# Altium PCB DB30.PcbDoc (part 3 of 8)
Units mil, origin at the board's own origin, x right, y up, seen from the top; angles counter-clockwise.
Board outline 3236.22 x 4456.69 mil, 8 copper layers (Top Layer, MidLayer1, MidLayer2, GND-Layer5, MidLayer3, VCC, MidLayer4, Bottom Layer), stack 61.8 mil thick; 219 components, 472 nets, 1811 pads, 1561 vias.
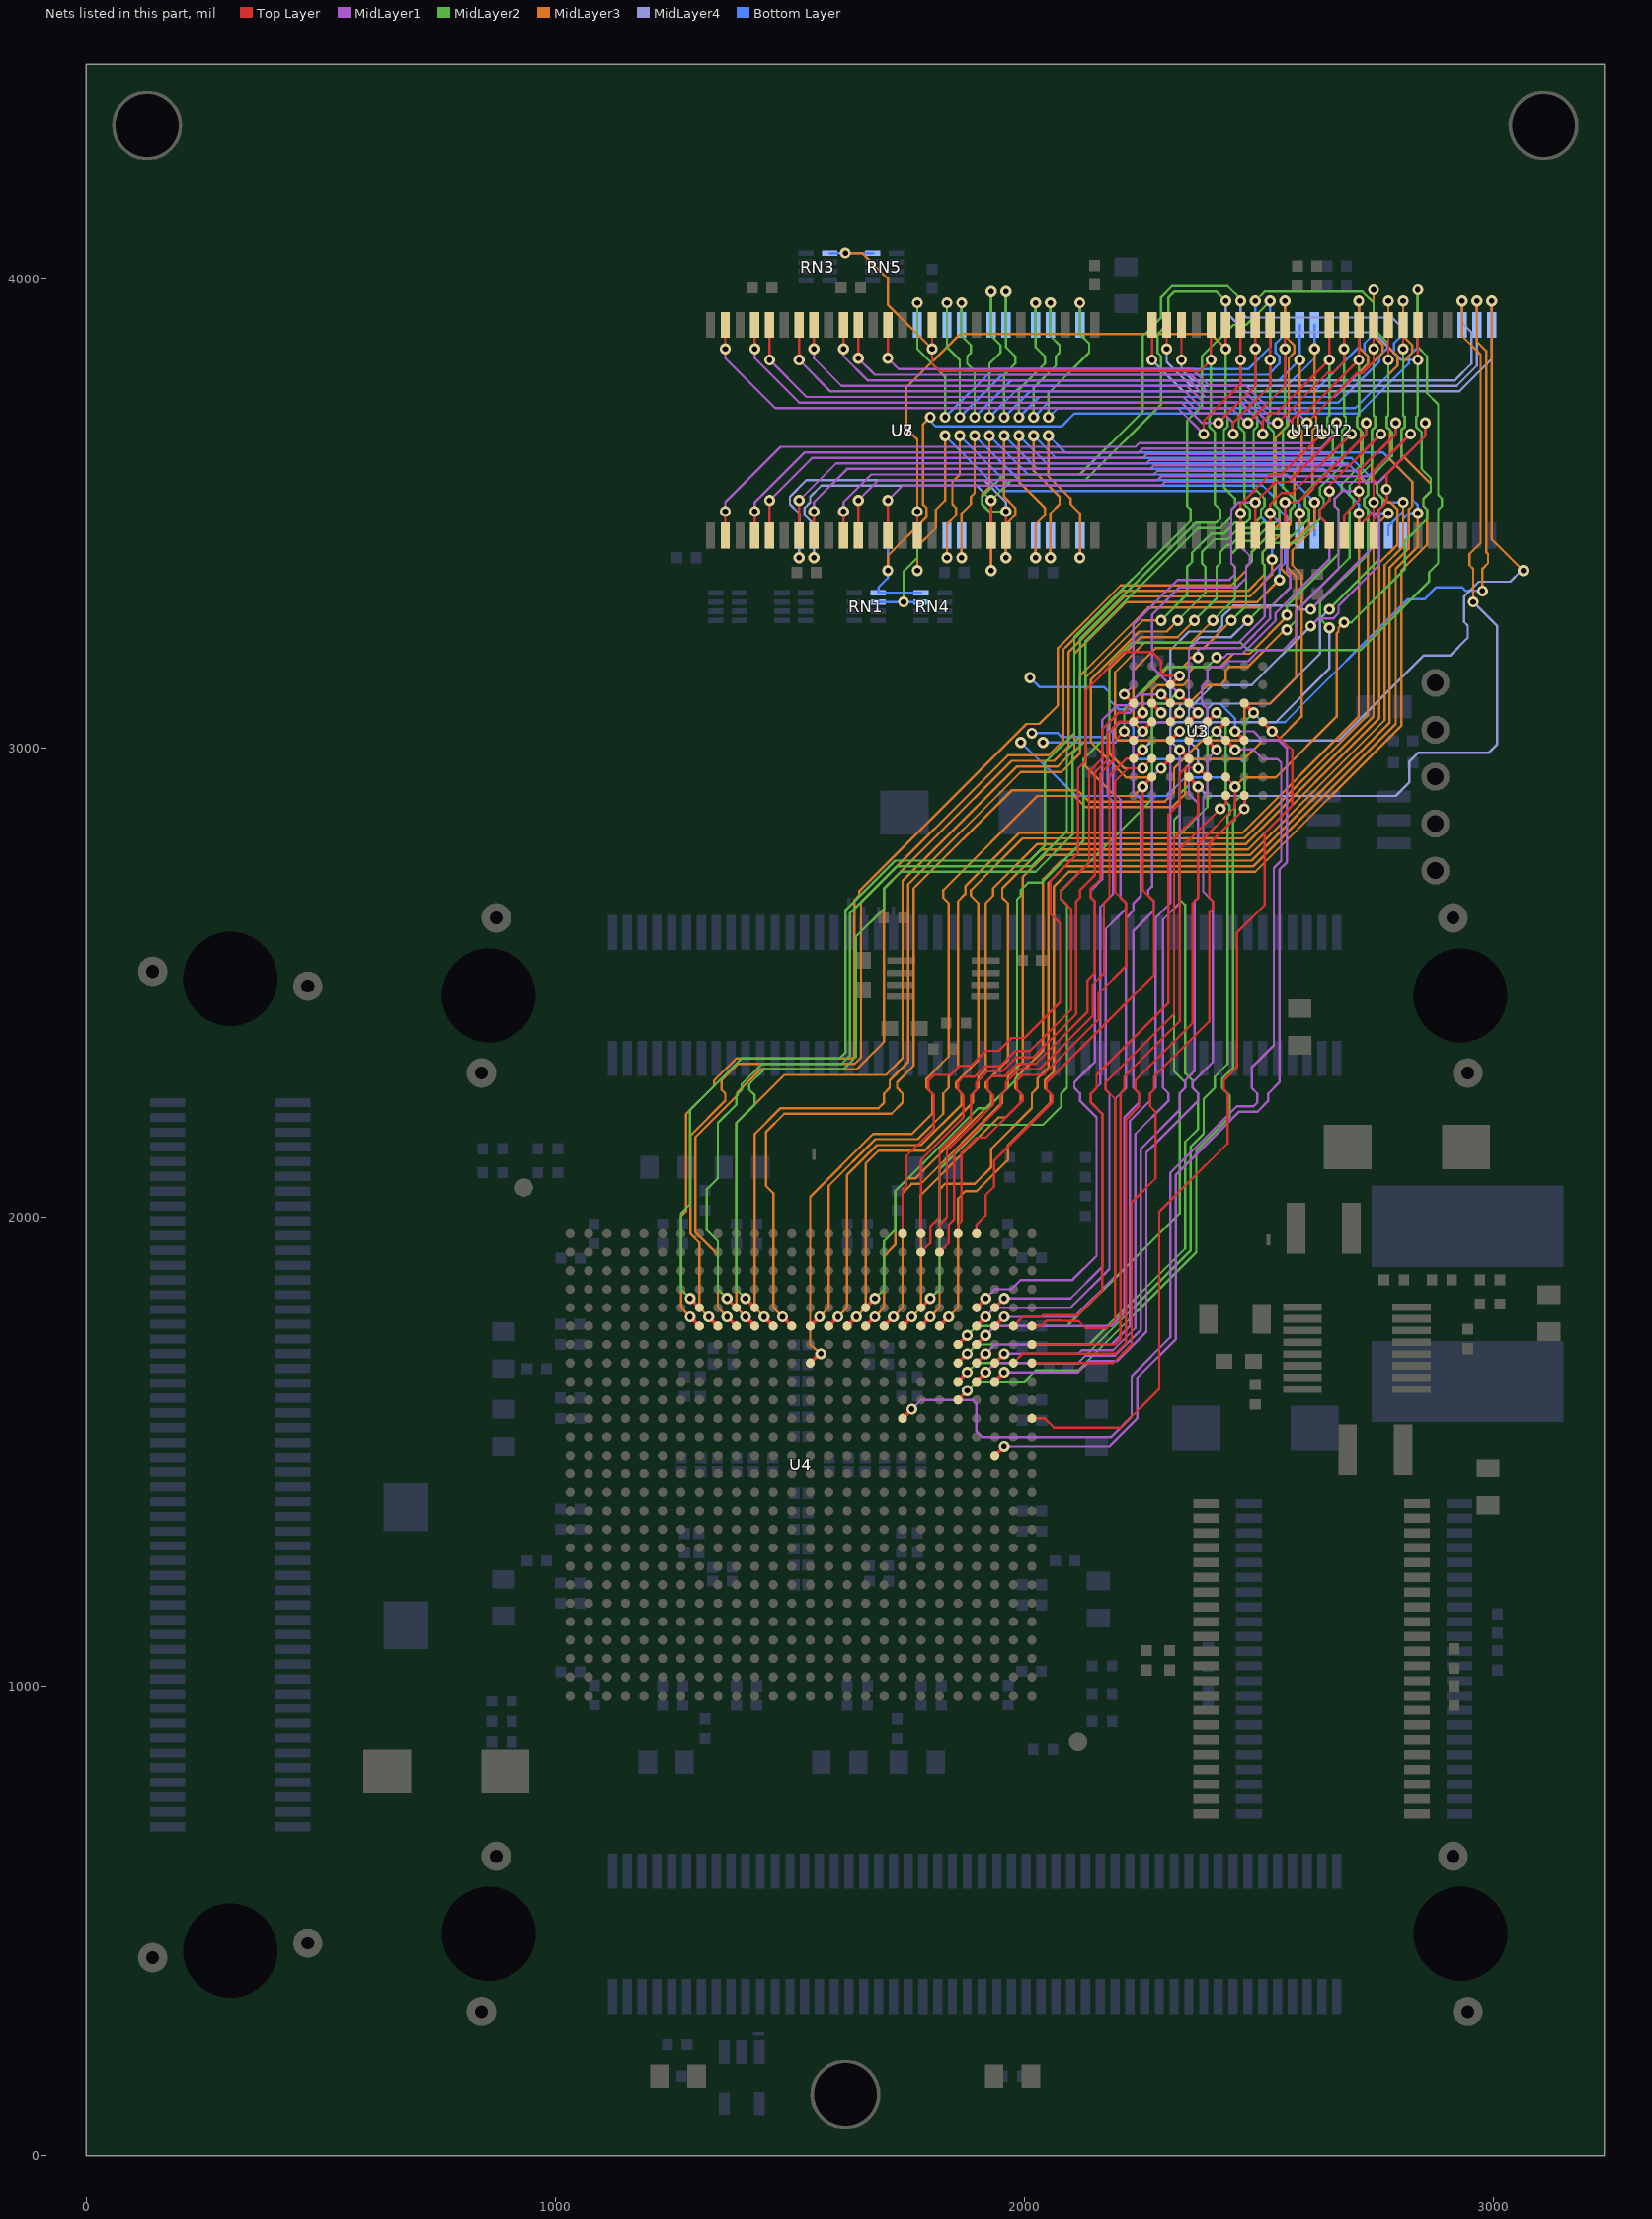
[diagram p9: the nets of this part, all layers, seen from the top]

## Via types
v1: diameter 23.62, hole 11.81, Top Layer to Bottom Layer, 944 vias
v2: diameter 23.62, hole 11.81, Top Layer to Bottom Layer, tented both sides, 477 vias
v3: diameter 27.56, hole 15.75, Top Layer to Bottom Layer, 139 vias
v4: diameter 23.62, hole 11.81, Top Layer to Bottom Layer, tented top, 1 vias

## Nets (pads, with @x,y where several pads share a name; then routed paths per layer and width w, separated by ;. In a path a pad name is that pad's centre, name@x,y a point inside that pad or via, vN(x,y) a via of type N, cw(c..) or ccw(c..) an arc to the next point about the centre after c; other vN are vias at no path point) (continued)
BUS_A15: U3.C7 U4.H25 U7.20 U8.20 U11.26 U12.26 | length 4825.3
  Top Layer w5: U7.20@1929.13,3452.76 v2(1929.13,3527.55) ; U4.H25@1976.38,1688.98 1996.06,1708.66 2078.74,1708.66 2090.55,1708.66 2192.91,1708.66 2216.54,1732.28 2216.54,2208.66 2244.09,2236.22 2244.09,2263.78 2236.22,2271.65 2236.22,2291.34 2358.27,2413.39 2358.27,2669.29 2370.08,2681.1 2370.08,2795.28 2448.82,2874.02 v1(2448.82,2917.32) 2448.82,2918.31 U3.C7@2429.13,2937.99 ; v2(2838.58,3826.77) U11.26@2838.58,3901.57
  MidLayer2 w5: v2(1929.13,3527.55) 1972.44,3570.87 2129.92,3570.87 2291.34,3732.28 2291.34,3834.65 2283.46,3842.52 2283.46,3881.89 2293.31,3891.73 2307.09,3905.51 2307.09,3960.63 2318.9,3972.44 2409.45,3972.44 v2(2429.13,3952.76) ; v1(2681.1,3267.72) 2696.85,3267.72 2811.02,3381.89 2811.02,3440.94 2858.27,3488.19 2858.27,3507.87 2850.39,3515.75 2850.39,3531.5 2866.14,3547.25 2866.14,3574.8 2846.46,3594.49 2846.46,3673.23 2834.64,3685.04 2834.64,3704.72 2838.58,3708.66 v2(2838.58,3826.77)
  MidLayer3 w5: v1(2448.82,2917.32) 2468.5,2937.01 2535.43,2937.01 2665.35,3066.93 2665.35,3244.09 2669.29,3248.03 2669.29,3255.91 v1(2681.1,3267.72)
  MidLayer4 w5: v2(1551.18,3405.51) 1551.18,3476.38 1531.5,3496.06 1531.5,3511.81 1543.31,3523.62 1543.31,3535.43 1566.93,3559.06 1897.63,3559.06 v2(1929.13,3527.55) ; v2(2429.13,3952.76) 2429.13,3929.13 2472.44,3885.83 2744.09,3885.83 2803.15,3826.77 v2(2838.58,3826.77)
  Bottom Layer w5: v2(1551.18,3405.51) U8.20@1551.18,3452.76 ; U12.26@2429.13,3901.57 v2(2429.13,3952.76)
BUS_A16: U3.D7 U4.F25 U7.21 U8.21 U11.27 U12.27 | length 4895
  Top Layer w5: U7.21@1960.63,3452.76 v2(1960.63,3503.93) ; U4.F25@1976.38,1767.72 1996.06,1787.4 2000,1787.4 2031.5,1787.4 2035.43,1787.4 2039.37,1791.34 2078.74,1791.34 2090.55,1791.34 2114.17,1791.34 2165.35,1842.52 2165.35,2220.47 2141.73,2244.09 2141.73,2263.78 2153.54,2275.59 2153.54,2303.15 2307.09,2456.69 2307.09,2858.27 2330.71,2881.89 2330.71,2944.88 2343.51,2957.68 v1@2370.08,2957.68 ; v2(2807.09,3850.39) U11.27@2807.09,3901.57
  Top Layer w7.87: v1@2370.08,2957.68 U3.D7@2389.76,2937.99
  MidLayer2 w5: v2(1960.63,3503.93) 1925.2,3503.93 1909.45,3519.68 1909.45,3535.43 1925.2,3551.18 1956.69,3582.68 2118.11,3582.68 2251.97,3716.54 2251.97,3877.95 2291.34,3917.32 2291.34,3960.63 2314.96,3984.25 2433.07,3984.25 2460.63,3956.69 v2(2460.63,3952.76) ; v1(2649.61,3295.28) 2755.91,3401.57 2755.91,3507.87 2763.78,3515.75 2763.78,3531.5 2751.97,3543.31 2751.97,3562.99 2803.15,3614.17 2803.15,3677.17 2811.02,3685.04 2811.02,3704.72 2807.09,3708.66 v2(2807.09,3850.39)
  MidLayer4 w5: v2(1519.68,3405.51) 1519.68,3500 1500,3519.68 1500,3535.43 1535.43,3570.87 1913.38,3570.87 1960.63,3523.63 v2(1960.63,3503.93) ; v1(2370.08,2956.69) 2370.08,2996.06 2350.39,3015.75 2350.39,3043.31 2362.2,3055.12 2377.95,3055.12 2389.76,3066.93 2389.76,3082.68 2401.57,3094.49 2523.62,3094.49 2629.92,3200.79 2629.92,3275.59 v1(2649.61,3295.28) ; v2(2460.63,3952.76) 2460.63,3929.13 2472.44,3917.32 2783.46,3917.32 2807.09,3893.7 v2(2807.09,3850.39)
  Bottom Layer w5: v2(1519.68,3405.51) U8.21@1519.68,3452.76 ; U12.27@2460.63,3901.57 v2(2460.63,3952.76)
BUS_A17: U3.E7 U4.F26 U11.42 U12.42 | length 4093.1
  Top Layer w5: U4.F26@2015.75,1767.72 2035.43,1767.72 2047.24,1779.53 2078.74,1779.53 2089.57,1778.54 2115.16,1778.54 2129.92,1763.78 2176.18,1763.78 2192.91,1780.51 2192.91,2251.97 2173.23,2271.65 2173.23,2287.4 2318.9,2433.07 2318.9,2807.09 2370.08,2858.27 v1(2370.08,2917.32) ; v2(2334.64,3826.77) U11.42@2334.64,3901.57
  Top Layer w7.87: U3.E7@2350.39,2937.99 v1(2370.08,2917.32)
  MidLayer3 w5: v2(2933.07,3952.76) 2933.07,3877.95 2972.44,3838.58 2972.44,3437.01 2948.82,3413.39 2948.82,3389.76 2956.69,3381.89 v1(2956.69,3311.02)
  MidLayer4 w5: v2(2334.64,3826.77) 2334.64,3807.09 2358.27,3783.46 2917.32,3783.46 2952.76,3818.9 2952.76,3885.83 2933.07,3905.51 v2(2933.07,3952.76) ; v1(2370.08,2917.32) 2389.76,2897.64 2791.34,2897.64 2820,2926.3 2820,2970 2840,2990 2990,2990 3007.87,3007.87 3007.87,3259.84 v1(2956.69,3311.02)
  Bottom Layer w5: U12.42@2933.07,3901.57 v2(2933.07,3952.76)
BUS_A18: U3.B3 U4.K22 U11.43 U12.43 | length 4100.1
  Top Layer w5: v2(2303.15,3850.39) U11.43@2303.15,3901.57 ; v1(2488.19,3074.8) v1@2488.19,3075.8
  Top Layer w7.87: U4.K22@1858.27,1610.24 v1(1877.95,1629.92) ; U3.B3@2468.5,3095.47 v1@2488.19,3075.79
  MidLayer2 w5: v1(1877.95,1629.92) 1897.64,1649.61 2000,1649.61 2023.62,1673.23 2078.74,1673.23 2090.55,1673.23 2114.17,1673.23 2366.14,1925.2 2366.14,2141.73 2437.01,2212.6 2437.01,2259.84 2421.26,2275.59 2421.26,2295.28 2444.88,2318.9 2444.88,2673.23 2444.88,2842.52 2448.82,2846.46 2448.82,2885.83 2468.5,2905.51 2468.5,2976.38 2468.5,3055.12 v1(2488.19,3074.8)
  MidLayer3 w5: v2(2964.57,3952.76) 2964.57,3866.14 2984.25,3846.46 2984.25,3417.32 2988.19,3413.39 2988.19,3393.7 2976.38,3381.89 v1(2976.38,3334.65)
  MidLayer4 w5: v2(2303.15,3850.39) 2303.15,3822.83 2354.33,3771.65 2921.26,3771.65 2964.57,3814.96 v2(2964.57,3952.76)
  Bottom Layer w5: v1(2488.19,3074.8) 2507.87,3055.12 2555.12,3055.12 2816.68,3316.68 2852.11,3316.68 2877.95,3342.52 2933.07,3342.52 2940.94,3334.65 v1(2976.38,3334.65) ; U12.43@2964.57,3901.57 v2(2964.57,3952.76)
BUS_A19: U3.C4 U4.H22 U11.44 U12.44 | length 4283.9
  Top Layer w5: v2(2271.65,3826.77) U11.44@2271.65,3901.57
  Top Layer w7.87: U4.H22@1858.27,1688.98 v1(1877.95,1708.66) ; v1(2409.45,3035.43) U3.C4@2429.13,3056.1
  MidLayer2 w5: v1(1877.95,1708.66) 1897.64,1728.35 2078.74,1728.35 2090.55,1728.35 2137.8,1728.35 2342.52,1933.07 2342.52,2160.43 2370.08,2187.99 2370.08,2263.78 2358.27,2275.59 2358.27,2291.34 2342.52,2307.09 2342.52,2665.35 2330.71,2677.17 2330.71,2814.96 2389.76,2874.02 2389.76,3015.75 v1(2409.45,3035.43)
  MidLayer3 w5: v2(2996.06,3952.76) 2996.06,3633.86 2996.06,3444.88 v1(3062.99,3377.95)
  MidLayer4 w5: v2(2271.65,3826.77) 2338.58,3759.84 2926.67,3759.84 2996.06,3829.23 v2(2996.06,3952.76) ; v1(2409.45,3035.43) 2429.13,3015.75 2669.29,3015.75 2850.39,3196.85 2906.85,3196.85 2944.88,3234.88 2944.88,3260.83 2937.01,3268.7 2937.01,3322.83 2968.5,3354.33 3035.43,3354.33 3059.06,3377.95 v1(3062.99,3377.95)
  Bottom Layer w5: U12.44@2996.06,3901.57 v2(2996.06,3952.76)
BUS_A20: U3.D5 U4.J24 U11.28 U12.28 | length 3365.1
  Top Layer w5: v2(2775.59,3826.77) U11.28@2775.59,3901.57
  Top Layer w7.87: U4.J24@1937.01,1649.61 v1(1956.69,1669.29) ; U3.D5@2389.76,3016.73 v1(2409.45,2996.06)
  MidLayer1 w5: v1(1956.69,1669.29) 2078.74,1669.29 2094.49,1669.29 2114.17,1669.29 2137.8,1692.91 2196.85,1692.91 2259.84,1755.91 2259.84,2137.8 2370.08,2248.03 2370.08,2263.78 2358.27,2275.59 2358.27,2287.4 2401.57,2330.71 2401.57,2673.23 2380.91,2693.9 2380.91,2894.69 2389.76,2903.54 2389.76,2976.38 v1(2409.45,2996.06)
  MidLayer2 w5: v2(2492.13,3952.76) 2511.81,3972.44 2720.47,3972.44 2744.09,3948.82 2744.09,3893.7 2775.59,3862.21 v2(2775.59,3826.77) 2775.59,3708.66 2771.65,3704.72 2771.65,3685.04 2783.46,3673.23 2783.46,3622.05 2732.28,3570.87 2732.28,3539.37 2724.41,3531.5 2724.41,3515.75 2732.28,3507.87 2732.28,3413.39 2629.92,3311.02 2629.92,3275.59 v1(2649.61,3255.91)
  MidLayer4 w5: v1(2409.45,2996.06) 2389.76,3015.75 2389.76,3043.31 2401.57,3055.12 2535.43,3055.12 2649.61,3169.29 v1(2649.61,3255.91)
  Bottom Layer w5: U12.28@2492.13,3901.57 v2(2492.13,3952.76)
BUS_A21: U3.D4 U4.J22 | length 1830.3
  Top Layer w7.87: U4.J22@1858.27,1649.61 v1(1877.95,1669.29) ; U3.D4@2389.76,3056.1 v1(2409.45,3074.8)
  MidLayer2 w5: v1(1877.95,1669.29) 1897.64,1688.98 2078.74,1688.98 2090.55,1688.98 2114.17,1688.98 2354.33,1929.14 2354.33,2150.59 2381.89,2178.15 2381.89,2251.97 2405.51,2275.59 2405.51,2299.21 2433.07,2326.77 2433.07,2749.01 2433.07,2854.33 2437.01,2858.27 2437.01,2877.95 2429.13,2885.83 2429.13,2909.45 2429.13,3055.12 v1(2409.45,3074.8)
BUS_A22: U3.C5 U4.L19 | length 2769
  Top Layer w7.87: U4.L19@1740.16,1570.87 v1(1759.84,1590.55) ; U3.C5@2429.13,3016.73 v1@2448.82,2997.05
  MidLayer1 w5: v1(1759.84,1590.55) 1779.53,1610.24 1889.76,1610.24 1897.64,1602.36 1897.64,1543.31 1909.45,1531.5 2043.31,1531.5 2078.74,1531.5 2090.55,1531.5 2185.04,1531.5 2228.35,1574.8 2228.35,1661.42 2311.02,1744.09 2311.02,2094.49 2452.76,2236.22 2488.19,2236.22 2496.06,2244.09 2496.06,2263.78 2484.25,2275.59 2484.25,2318.9 2531.5,2366.14 2531.5,2744.09 2547.24,2759.84 2547.24,2968.5 2539.37,2976.38 2507.87,2976.38 2487.2,2997.05 v1@2448.82,2997.05
  Bottom Layer w5: v1(2015.75,3031.5) 2070.87,3031.5 2078.74,3023.62 2173.23,3023.62 2204.72,3055.12 2220.47,3055.12 2232.28,3043.31 2232.28,3023.62 2240.16,3015.75 2429.13,3015.75 2447.83,2997.05 v1@2448.82,2997.05
  other v1: 2448.82,2996.06
BUS_A23: U3.B8 U4.H26 | length 2092.6
  Top Layer w5: U4.H26@2015.75,1688.98 2078.74,1688.98 2090.55,1688.98 2188.98,1688.98 2228.35,1728.35 2228.35,2031.5 2279.53,2082.68 2279.53,2224.41 2267.72,2236.22 2267.72,2263.78 2275.59,2271.65 2275.59,2299.21 2393.7,2417.32 2393.7,2649.61 2401.57,2657.48 2401.57,2673.23 2393.7,2681.1 2393.7,2731.56 ; 2393.7,2716.54 2393.7,2795.28 v1(2468.51,2870.08) U3.B8@2468.5,2898.62
  Bottom Layer w5: v1(2039.37,3011.81) 2193.9,3011.81 2197.83,3015.75 2224.41,3015.75 2232.28,3007.87 2232.28,2984.25 2240.16,2976.38 2460.63,2976.38 2468.51,2968.5 v1(2468.51,2870.08)
BUS_A24: U3.C8 U4.G26 | length 2012
  Top Layer w5: U4.G26@2015.75,1728.35 2078.74,1728.35 2090.55,1728.35 2192.91,1728.35 2204.72,1740.16 2204.72,2263.78 2212.6,2271.65 2212.6,2299.21 2330.71,2417.32 2330.71,2783.46 v1(2417.32,2870.08) 2429.14,2881.89 U3.C8@2429.13,2898.62
  Bottom Layer w5: v1(1992.13,3011.81) 2110.24,2897.64 2303.15,2897.64 2342.52,2937.01 2421.26,2937.01 2429.13,2929.13 2429.13,2881.89 v1(2417.32,2870.08)
BUS_D0: U3.E3 U4.E20 U7.2 U11.7 | length 3959.9
  Top Layer w5: U7.2@1362.21,3452.76 v2(1362.2,3503.93) ; U11.7@2460.63,3452.76 v1(2460.63,3500) 2460.63,3519.69 2523.62,3582.68 2547.24,3582.68 v2(2633.86,3669.29)
  Top Layer w7.87: U4.E20@1779.53,1807.09 v1(1799.21,1826.77) ; v1(2330.71,3114.17) U3.E3@2350.4,3095.48
  MidLayer1 w5: v2(1362.2,3503.93) 1362.2,3523.62 1480.31,3641.73 2236.22,3641.73 2244.09,3649.61 2614.17,3649.61 v2(2633.86,3669.29) ; v1(2330.71,3114.17) 2271.65,3173.23 2271.65,3283.46 2330.71,3342.52 2452.76,3342.52 2472.44,3362.2 2472.44,3385.83 2480.31,3393.7 2480.31,3409.45 2460.63,3429.13 v1(2460.63,3500)
  MidLayer2 w5: v1(1799.21,1826.77) 1818.9,1846.46 1818.9,2027.56 1818.9,2039.37 1818.9,2102.36 1913.38,2196.85 2039.37,2196.85 2078.74,2236.22 2078.74,2263.78 2090.55,2275.59 2090.55,2665.35 2078.74,2677.17 2078.74,2696.85 2094.49,2712.6 ; 2084.64,2702.76 2271.65,2889.77 2271.65,3086.61 2279.53,3094.49 2302.17,3094.49 2321.85,3114.17 v1(2330.71,3114.17)
BUS_D1: U3.H3 U4.A20 U7.4 U11.8 | length 3767.4
  Top Layer w5: U7.4@1425.2,3452.76 v2(1425.19,3503.93) ; U4.A20@1779.53,1964.57 1779.53,2027.56 1779.53,2039.37 1779.53,2122.05 1870.08,2212.6 1870.08,2259.84 1858.27,2271.65 1858.27,2287.4 1870.08,2299.21 1893.7,2299.21 1915.84,2321.36 1947.34,2321.36 1980.19,2354.21 2011.69,2354.21 2099.41,2441.93 2099.41,2656.5 2078.74,2677.17 2078.74,2696.85 2137.8,2755.91 2137.8,2949.54 2165.35,2977.1 2165.35,3039.37 2201.28,3075.3 2212.1,3075.3 U3.H3@2232.29,3095.48 ; U11.8@2492.13,3452.76 v1(2492.13,3523.62) 2535.43,3566.93 2562.99,3566.93 2665.35,3669.29 v2(2665.35,3692.91)
  Top Layer w7.87: v1(2212.6,3114.17) U3.H3@2232.29,3095.48
  MidLayer1 w5: v2(1425.19,3503.93) 1425.19,3523.62 1531.5,3629.92 2244.09,3629.92 2251.97,3637.8 2629.92,3637.8 2665.35,3673.23 v2(2665.35,3692.91) ; v1(2212.6,3114.17) 2232.28,3133.86 2232.28,3263.78 2326.77,3358.27 2437.01,3358.27 2448.82,3370.08 2448.82,3385.83 2440.94,3393.7 2440.94,3507.87 2456.69,3523.62 v1(2492.13,3523.62)
BUS_D2: U3.E4 U4.G22 U7.5 U11.9 | length 3971.7
  Top Layer w5: U7.5@1456.69,3452.76 v2(1456.69,3527.55) ; U11.9@2523.62,3452.76 v1(2523.62,3500) 2523.62,3519.69 2547.24,3543.31 2570.87,3543.31 v2(2696.85,3669.29)
  Top Layer w7.87: U4.G22@1858.27,1728.35 v1(1877.95,1748.03) ; U3.E4@2350.39,3056.1 v1(2370.08,3074.81)
  MidLayer1 w5: v2(1456.69,3527.55) 1547.24,3618.11 2251.97,3618.11 2259.84,3625.98 2653.54,3625.98 v2(2696.85,3669.29) ; v1(2370.08,3074.81) 2350.39,3094.5 2350.39,3208.66 2366.14,3224.41 2456.69,3224.41 2511.81,3279.53 2511.81,3358.27 2547.24,3393.7 2547.24,3476.38 v1(2523.62,3500)
  MidLayer2 w5: v1(1877.95,1748.03) 1897.64,1767.72 2078.74,1767.72 2090.55,1767.72 2330.71,2007.87 2330.71,2263.78 2342.52,2275.59 2342.52,2287.4 2318.9,2311.02 2318.9,2846.46 2330.71,2858.27 2330.71,2901.57 2350.39,2921.26 2350.39,3055.12 v1(2370.08,3074.81)
BUS_D3: U3.H4 U4.B20 U7.7 U11.10 | length 3759.1
  Top Layer w5: U7.7@1519.69,3452.76 v2(1519.68,3527.56) ; U4.B20@1779.53,1925.2 1799.21,1944.88 1799.21,1980.32 1818.9,2000 1818.9,2027.56 1818.9,2039.37 1818.9,2141.73 1885.83,2208.66 1885.83,2259.84 1897.64,2271.65 1897.64,2287.4 1921.26,2311.02 1952.76,2311.02 1982.28,2340.55 2017.72,2340.55 2110.24,2433.07 2110.24,2673.23 2118.11,2681.1 2118.11,2696.85 2149.61,2728.35 2149.61,2947.21 2177.17,2974.77 2177.17,3031.5 2201.78,3056.11 U3.H4@2232.28,3056.1 ; U11.10@2555.12,3452.76 v1(2555.12,3523.62) 2582.68,3523.62 2640.75,3581.69 2728.35,3669.29 v2(2728.35,3692.91)
  Top Layer w7.87: U3.H4@2232.28,3056.1 v1@2251.47,3075.3
  MidLayer1 w5: v2(1519.68,3527.56) 1598.43,3606.3 2259.84,3606.3 2267.72,3614.17 2673.23,3614.17 2728.35,3669.29 v2(2728.35,3692.91) ; v1(2370.08,3192.91) 2370.08,3208.66 2374.02,3212.6 2460.63,3212.6 2523.62,3275.59 2523.62,3299.21 2566.93,3342.52 2566.93,3370.08 2559.06,3377.95 2559.06,3496.06 2555.12,3500 v1(2555.12,3523.62)
  MidLayer3 w5: v1(2251.97,3074.8) 2251.97,3118.11 2255.91,3122.05 2307.09,3173.23 2338.58,3173.23 2350.39,3185.04 2350.39,3188.98 2354.33,3192.91 v1(2370.08,3192.91)
BUS_D4: U3.H5 U4.A21 U7.8 U11.13 | length 3722.5
  Top Layer w5: U7.8@1551.18,3452.76 v2(1551.18,3503.94) ; U4.A21@1818.9,1964.57 1818.9,1984.25 1834.65,2000 1834.65,2027.56 1834.65,2039.37 1834.65,2141.73 1933.07,2240.16 1933.07,2259.84 1921.26,2271.65 1921.26,2291.34 1930.12,2300.2 1957.68,2300.2 1984.25,2326.77 2023.62,2326.77 2133.86,2437.01 2133.86,2503.94 2149.61,2519.69 2149.61,2673.23 2141.73,2681.1 2141.73,2700.79 2161.42,2720.47 2161.42,2944.88 2188.98,2972.44 2188.98,3011.81 v1(2212.6,3035.43) U3.H5@2232.28,3016.73 ; U11.13@2649.61,3452.76 2649.61,3472.44 2629.92,3492.13 2629.92,3507.87 2649.61,3527.56 2649.61,3559.06 v2(2759.84,3669.29)
  MidLayer1 w5: v2(1551.18,3503.94) 1551.18,3523.62 1622.05,3594.49 2267.72,3594.49 2275.59,3602.36 2692.91,3602.36 v2(2759.84,3669.29) ; v1(2409.45,3192.91) 2425.2,3192.91 2433.07,3200.79 2464.57,3200.79 2535.43,3271.65 2535.43,3287.4 2649.61,3401.57 2649.61,3472.44 2629.92,3492.13 2629.92,3507.87 2649.61,3527.56 v1(2649.61,3547.24)
  MidLayer2 w5: v1(2212.6,3035.43) 2212.6,3082.68 2303.15,3173.23 2389.76,3173.23 v1(2409.45,3192.91)
BUS_D5: U3.E5 U4.J23 U7.10 U11.14 | length 4159.2
  Top Layer w5: U7.10@1614.17,3452.76 v2(1614.17,3503.93) ; U11.14@2681.1,3452.76 2681.1,3496.06 2712.6,3527.56 v1(2712.6,3547.24) 2712.6,3590.55 2791.34,3669.29 v2(2791.34,3692.91)
  Top Layer w7.87: U4.J23@1897.64,1649.61 v1(1917.32,1669.29) ; U3.E5@2350.39,3016.73 v1(2370.08,3035.43)
  MidLayer1 w5: v2(1614.17,3503.93) 1614.17,3523.62 1673.23,3582.68 2275.59,3582.68 2283.46,3590.55 2712.6,3590.55 2791.34,3669.29 v2(2791.34,3692.91) ; v1(1917.32,1669.29) 1937.01,1688.98 2078.74,1688.98 2094.49,1688.98 2114.17,1688.98 2129.92,1704.72 2192.91,1704.72 2248.03,1759.84 2248.03,2145.67 2330.71,2228.35 2330.71,2263.78 2342.52,2275.59 2342.52,2291.34 2362.2,2311.02 2362.2,2673.23 2370.08,2681.1 2370.08,2720.47 ; 2370.08,2704.72 2370.08,2720.47 ; v1(2712.6,3547.24) 2677.17,3547.24 2661.42,3531.5 2661.42,3515.75 2669.29,3507.87 2669.29,3381.89 2578.74,3291.34 2578.74,3236.22 2551.18,3208.66 2500,3208.66 2476.38,3185.04 2433.07,3185.04 2421.26,3173.23 2397.64,3173.23 2389.76,3165.35 2389.76,3141.73 2377.95,3129.92 2377.95,3094.49 2389.76,3082.68 2389.76,3055.12 v1(2370.08,3035.43) 2350.39,3015.75 2350.39,2901.57 2370.08,2881.89 2370.08,2720.47
BUS_D6: U3.H6 U4.B21 U7.11 U11.15 | length 3743.7
  Top Layer w5: U7.11@1645.67,3452.76 v2(1645.66,3527.55) ; U4.B21@1818.9,1925.2 1838.58,1944.88 1838.58,1948.82 1838.58,1980.32 1838.58,1984.25 1850.39,1996.06 1850.39,2027.56 1850.39,2039.37 1850.39,2137.8 1948.82,2236.22 1948.82,2259.84 1960.63,2271.65 1960.63,2287.4 1988.19,2314.96 2031.5,2314.96 2145.67,2429.13 2145.67,2496.06 2169.29,2519.69 2169.29,2669.29 2181.1,2681.1 2181.1,2940.94 2217.52,2977.37 U3.H6@2232.28,2977.36 ; U11.15@2712.6,3452.76 2712.6,3472.44 2744.09,3503.94 v1(2744.09,3523.62) 2744.09,3590.55 v2(2822.83,3669.29)
  Top Layer w7.87: U3.H6@2232.28,2977.36 v1@2251.97,2997.05
  MidLayer1 w5: v2(1645.66,3527.55) 1688.98,3570.87 2283.46,3570.87 2291.34,3578.74 2732.28,3578.74 v2(2822.83,3669.29) ; v1(2610.24,3295.28) 2744.09,3429.13 v1(2744.09,3523.62)
  MidLayer4 w5: v1(2251.97,2996.06) 2271.65,3015.75 2271.65,3043.31 2283.46,3055.12 2303.15,3055.12 2311.02,3062.99 2311.02,3208.66 2350.39,3248.03 2409.45,3248.03 2421.26,3259.84 2421.26,3279.53 2444.88,3303.15 2578.74,3303.15 2586.61,3295.28 v1(2610.24,3295.28)
BUS_D7: U3.E6 U4.H24 U7.13 U11.16 | length 4081
  Top Layer w5: U7.13@1708.66,3452.76 v2(1708.66,3527.55) ; U11.16@2744.09,3452.76 2744.09,3488.19 2755.91,3500 2755.91,3507.87 2771.65,3523.62 v1(2771.65,3551.18) 2771.65,3582.68 2854.33,3665.35 v2(2854.33,3692.91)
  Top Layer w7.87: U4.H24@1937.01,1688.98 v1(1956.69,1708.66) ; v1@2330.71,2997.05 2331.2,2996.56 U3.E6@2350.39,2977.36
  MidLayer1 w5: v2(1708.66,3527.55) 1740.16,3559.06 2291.34,3559.06 2299.21,3566.93 2755.91,3566.93 2854.33,3665.35 v2(2854.33,3692.91) ; v1(1956.69,1708.66) 2078.74,1708.66 2094.49,1708.66 2114.17,1708.66 2122.05,1716.54 2188.98,1716.54 2236.22,1763.78 2236.22,2177.17 2307.09,2248.03 2307.09,2263.78 2295.28,2275.59 2295.27,2633.86 2330.71,2669.29 2330.71,2700.79 ; 2330.71,2681.1 v1(2330.71,2996.06) v1@2330.71,2997.05 ; v1(2610.24,3259.84) 2625.98,3275.59 2657.48,3275.59 2669.29,3287.4 2669.29,3303.15 2755.91,3389.76 2755.91,3507.87 2771.65,3523.62 v1(2771.65,3551.18)
  MidLayer4 w5: v1(2330.71,2996.06) 2311.02,3015.75 2311.02,3043.31 2322.83,3055.12 2338.58,3055.12 2350.39,3066.93 2350.39,3082.68 2401.57,3133.86 2484.25,3133.86 v1(2610.24,3259.84)
BUS_D8: U3.F3 U4.E23 U7.42 U11.29 | length 4003.9
  Top Layer w5: v2(1708.66,3830.71) U7.42@1708.66,3901.57 ; v2(2602.36,3692.91) 2708.17,3798.72 2719.98,3798.72 2744.09,3822.83 v2(2744.09,3850.39) U11.29@2744.09,3901.57
  Top Layer w7.87: U4.E23@1897.64,1807.09 v1(1917.32,1826.77) ; v1@2291.34,3115.16 2291.83,3114.67 U3.F3@2311.03,3095.48
  MidLayer1 w5: v2(1708.66,3830.71) 1732.28,3807.09 2358.27,3807.09 2393.7,3771.65 2472.44,3771.65 2519.69,3724.41 2570.87,3724.41 v2(2602.36,3692.91) ; v1(1917.32,1826.77) 1937.01,1846.46 1972.44,1846.46 1992.13,1866.14 2078.74,1866.14 2090.55,1866.14 2102.36,1866.14 2153.54,1917.32 2153.54,2212.6 2118.11,2248.03 2118.11,2263.78 2106.3,2275.59 2106.3,2287.4 2149.61,2330.71 2149.61,2645.67 2149.61,2673.23 2141.73,2681.1 2141.73,2696.85 2165.35,2720.47 2165.35,3059.06 2196.85,3090.55 2220.47,3090.55 2244.09,3114.17 v1(2291.34,3114.17)
  MidLayer2 w5: v1(2559.06,3251.97) 2578.74,3271.65 2578.74,3291.34 2692.91,3405.51 2692.91,3507.87 2700.79,3515.75 2700.79,3531.5 2692.91,3539.37 2692.91,3559.06 2740.16,3606.3 2740.16,3677.17 2748.03,3685.04 2748.03,3704.72 2744.09,3708.66 v2(2744.09,3850.39)
  MidLayer3 w5: v1(2291.34,3114.17) 2311.02,3094.49 2350.39,3094.49 2389.76,3133.86 2417.32,3133.86 2429.13,3145.67 2429.13,3165.35 2437.01,3173.23 2476.38,3173.23 2555.12,3251.97 v1(2559.06,3251.97)
BUS_D9: U3.G3 U4.E24 U7.44 U11.30 | length 4069.8
  Top Layer w5: v2(1645.67,3830.71) U7.44@1645.67,3901.57 ; v2(2570.87,3669.29) 2570.87,3700.79 2586.61,3716.54 2602.36,3716.54 v2(2712.6,3826.77) U11.30@2712.6,3901.57
  Top Layer w7.87: U4.E24@1937.01,1807.09 v1(1956.69,1826.77) ; U3.G3@2271.65,3095.48 v1(2291.34,3074.8)
  MidLayer1 w5: v2(1645.67,3830.71) 1681.1,3795.28 2354.33,3795.28 2389.76,3759.84 2469,3759.84 2516.24,3712.6 2551.18,3712.6 2570.87,3692.91 v2(2570.87,3669.29) ; v1(1956.69,1826.77) 2078.74,1826.77 2090.55,1826.77 2098.43,1826.77 2165.35,1893.7 2165.35,2220.47 2141.73,2244.09 2141.73,2263.78 2161.42,2283.46 2161.42,2661.42 2188.98,2688.98 2188.98,2724.41 ; 2188.98,2700.79 2188.98,2885.83 2177.17,2897.64 2177.17,3051.18 2200.79,3074.8 2224.41,3074.8 2244.09,3094.49 2271.65,3094.49 v1(2291.34,3074.8)
  MidLayer2 w5: v1(2559.06,3283.46) 2559.06,3303.15 2669.29,3413.39 2669.29,3507.87 2661.42,3515.75 2661.42,3531.5 2676.18,3546.26 2676.18,3562.01 2720.47,3606.3 2720.47,3673.23 2708.66,3685.04 2708.66,3704.72 2712.6,3708.66 v2(2712.6,3826.77)
  MidLayer3 w5: v1(2291.34,3074.8) 2271.65,3094.49 2271.65,3122.05 2283.46,3133.86 2338.58,3133.86 2350.39,3145.67 2350.39,3161.42 2362.2,3173.23 2417.32,3173.23 2444.88,3200.79 2480.31,3200.79 2559.06,3279.53 v1(2559.06,3283.46)
BUS_D10: U3.F4 U4.F23 U7.45 U11.31 | length 4043.8
  Top Layer w5: v2(1614.17,3850.39) U7.45@1614.17,3901.57 ; v2@2537.4,3694.88 2539.37,3694.88 2541.34,3694.88 2646.65,3800.2 2658.46,3800.2 2681.1,3822.83 v2(2681.1,3850.39) U11.31@2681.1,3901.57
  Top Layer w7.87: U4.F23@1897.64,1767.72 v1(1917.32,1787.4) ; U3.F4@2311.02,3056.1 v1(2330.71,3074.8)
  MidLayer1 w5: v2(1614.17,3850.39) 1614.17,3834.65 1665.35,3783.46 2350.39,3783.46 2385.83,3748.03 2464.57,3748.03 2519.69,3692.91 v2(2539.37,3692.91) ; v1(1917.32,1787.4) 1937.01,1807.09 2078.74,1807.09 2090.55,1807.09 2098.43,1807.09 2181.1,1889.76 2181.1,2263.78 2173.23,2271.66 2173.23,2614.17 2216.53,2657.48 2216.53,2669.29 2204.72,2681.1 2204.72,2708.66 ; 2204.72,2700.79 2204.72,2889.76 2188.98,2905.51 2188.98,3043.31 2200.79,3055.12 2311.02,3055.12 v1(2330.71,3074.8)
  MidLayer2 w5: v1(2476.38,3271.65) 2511.81,3307.09 2511.81,3389.76 2507.87,3393.7 2507.87,3417.32 2527.56,3437.01 2578.74,3437.01 2629.92,3488.19 2629.92,3507.87 2637.8,3515.75 2637.8,3531.5 2629.92,3539.37 2629.92,3555.12 2677.16,3602.36 2677.16,3677.17 2685.04,3685.04 2685.04,3704.72 2681.1,3708.66 v2(2681.1,3850.39)
  MidLayer4 w5: v1(2330.71,3074.8) 2330.71,3090.55 2334.65,3094.49 2342.52,3094.49 2350.39,3102.36 2350.39,3212.6 2374.02,3236.22 2440.94,3236.22 v1(2476.38,3271.65)
BUS_D11: U3.G4 U4.F24 U7.47 U11.32 | length 4009.9
  Top Layer w5: v2(1551.18,3850.39) U7.47@1551.18,3901.57 ; v2(2507.87,3669.29) 2507.87,3696.85 2523.62,3712.6 2535.43,3712.6 v2(2649.61,3826.77) U11.32@2649.61,3901.57
  Top Layer w7.87: U4.F24@1937.01,1767.72 v1(1956.69,1787.4) ; v1(2251.97,3035.43) U3.G4@2271.65,3056.1
  MidLayer1 w5: v2(1551.18,3850.39) 1551.18,3830.71 1610.24,3771.65 2346.46,3771.65 2381.89,3736.22 2460.63,3736.22 2507.87,3688.98 v2(2507.87,3669.29) ; v1(1956.69,1787.4) 2078.74,1787.4 2090.55,1787.4 2106.3,1787.4 2192.91,1874.02 2192.91,2251.97 2216.53,2275.59 2216.54,2637.8 2232.28,2653.54 2232.28,2669.29 2248.03,2685.04 2248.03,2889.76 2232.28,2905.51 2232.28,3015.75 v1(2251.97,3035.43)
  MidLayer2 w5: v1(2440.94,3271.65) 2472.44,3303.15 2472.44,3385.83 2484.25,3397.64 2484.25,3417.32 2519.69,3452.76 2570.87,3452.76 2606.3,3488.19 2606.3,3507.87 2598.43,3515.75 2598.43,3543.31 2657.48,3602.36 2657.48,3673.23 2645.67,3685.04 2645.67,3704.72 2649.61,3708.66 v2(2649.61,3826.77)
  MidLayer3 w5: v1(2251.97,3035.43) 2232.28,3055.12 2232.28,3165.35 2279.53,3212.6 2381.89,3212.6 v1(2440.94,3271.65)
BUS_D12: U3.F5 U4.H23 U7.48 U11.35 | length 4398.1
  Top Layer w5: v2(1519.68,3826.77) U7.48@1519.69,3901.57 ; v2(2476.38,3692.91) 2555.12,3771.65 v2(2555.12,3850.39) U11.35@2555.12,3901.57
  Top Layer w7.87: U4.H23@1897.64,1688.98 v1(1917.32,1708.66) ; U3.F5@2311.02,3016.73 v1(2330.71,3035.43)
  MidLayer1 w5: v2(1519.68,3826.77) 1586.6,3759.84 2342.52,3759.84 2377.95,3724.41 2440.94,3724.41 2472.44,3692.91 v2(2476.38,3692.91) ; v1(1917.32,1708.66) 1937.01,1728.35 ; 2051.18,1728.35 1937.01,1728.35 ; 2192.91,1736.22 2185.04,1728.35 ; v1@2326.78,3039.37 2330.22,3035.93 v1(2330.71,3035.43) 2311.02,3015.75 2311.02,2669.29 2279.53,2637.79 2279.53,2275.59 2267.72,2263.78 2267.72,2248.03 2224.41,2204.72 2224.41,1767.72 2185.04,1728.35 ; 1937.01,1728.35 2078.74,1728.35 2094.49,1728.35 2114.17,1728.35 2185.04,1728.35
  MidLayer2 w5: v1(2401.57,3271.65) 2448.82,3318.9 2448.82,3385.83 2440.94,3393.7 2440.94,3413.39 2468.5,3440.94 2488.19,3440.94 2513.78,3466.54 2541.34,3466.54 2547.24,3472.44 2566.93,3492.13 2566.93,3507.87 2574.8,3515.75 2574.8,3531.5 2555.12,3551.18 2551.18,3555.12 2551.18,3677.17 2559.05,3685.04 2559.05,3704.72 2555.12,3708.66 v2(2555.12,3850.39)
  MidLayer3 w5: v1(2330.71,3035.43) 2311.02,3015.75 2200.79,3015.75 2192.91,3023.62 2192.91,3161.42 2255.91,3224.41 2354.33,3224.41 v1(2401.57,3271.65)
BUS_D13: U3.G6 U4.A22 U7.50 U11.36 | length 3852.8
  Top Layer w5: v2(1456.69,3826.77) U7.50@1456.69,3901.57 ; U4.A22@1858.27,1964.57 1858.27,1984.25 1866.14,1992.13 1866.14,2027.56 1866.14,2039.37 1866.14,2137.8 1897.64,2169.29 1917.32,2169.29 1996.06,2248.03 1996.06,2259.84 1984.25,2271.65 1984.25,2291.34 1996.06,2303.15 2039.37,2303.15 2158.46,2422.24 2158.46,2477.36 2216.54,2535.43 2216.54,2669.29 2192.91,2692.91 2192.91,2838.58 ; 2192.91,2822.83 2192.91,2929.14 2220.47,2956.69 v1(2251.97,2956.69) ; v1@2251.97,2957.68 U3.G6@2271.65,2977.36 ; v2(2444.88,3669.29) 2444.88,3692.91 2523.62,3771.65 v2(2523.62,3826.77) U11.36@2523.62,3901.57
  MidLayer1 w5: v2(1456.69,3826.77) 1535.43,3748.03 2338.58,3748.03 2374.02,3712.6 2425.2,3712.6 2444.88,3692.91 v2(2444.88,3669.29)
  MidLayer2 w5: v1(2362.2,3271.65) 2409.45,3318.9 2409.45,3385.83 2417.32,3393.7 2417.32,3417.32 2433.07,3433.07 2440.94,3433.07 2464.57,3456.69 2484.25,3456.69 2507.87,3480.32 2523.62,3480.32 2535.43,3480.31 2543.31,3488.19 2543.31,3507.87 2531.5,3519.69 2531.5,3673.23 2519.68,3685.04 2519.68,3704.72 2523.62,3708.66 v2(2523.62,3826.77)
  MidLayer3 w5: v1(2251.97,2956.69) 2212.6,2956.69 2181.1,2988.19 2181.1,3169.29 2248.03,3236.22 2326.77,3236.22 v1(2362.2,3271.65)
BUS_D14: U3.F6 U4.G23 U7.51 U11.37 | length 4209.6
  Top Layer w5: v2(1425.2,3850.39) U7.51@1425.2,3901.57 ; v2(2413.38,3692.91) 2492.13,3771.65 v2(2492.13,3850.39) U11.37@2492.13,3901.57
  Top Layer w7.87: U4.G23@1897.64,1728.35 v1(1917.32,1748.03) ; v1@2290.85,2957.19 U3.F6@2311.02,2977.36
  MidLayer1 w5: v2(1425.2,3850.39) 1425.2,3830.71 1519.69,3736.22 2334.65,3736.22 2377.95,3692.91 v2(2413.38,3692.91) ; v1(1917.32,1748.03) 1937.01,1767.72 2078.74,1767.72 2090.55,1767.72 2185.04,1767.72 2208.66,1791.34 2212.6,1795.28 2212.6,2212.6 2244.09,2244.09 2244.09,2263.78 2232.28,2275.59 2232.28,2610.24 2275.59,2653.54 2275.59,2673.23 2263.78,2685.04 2263.78,2696.85 2271.65,2704.72 2271.65,2937.01 v1(2291.34,2956.69) v1@2291.34,2957.68
  MidLayer2 w5: v1(2326.77,3271.65) 2385.83,3330.71 2385.83,3385.83 2377.95,3393.7 2377.95,3417.32 2405.51,3444.88 2433.07,3444.88 2456.69,3468.5 2480.31,3468.5 2503.94,3492.13 2503.94,3507.87 2511.81,3515.75 2511.81,3531.5 2492.13,3551.18 2488.19,3555.12 2488.19,3677.17 2496.06,3685.04 2496.06,3704.72 2492.13,3708.66 v2(2492.13,3850.39)
  MidLayer3 w5: v1(2291.34,2956.69) 2271.66,2937.01 2216.54,2937.01 2141.73,3011.81 2141.73,3145.67 2244.09,3248.03 2303.15,3248.03 v1(2326.77,3271.65)
BUS_D15: U3.G7 U4.A23 U7.53 U11.38 | length 3816.2
  Top Layer w5: v2(1362.2,3850.39) U7.53@1362.21,3901.57 ; U4.A23@1897.64,1964.57 1897.64,1984.25 1917.32,2003.94 1917.32,2027.56 1917.32,2039.37 1917.32,2047.24 1934.88,2064.8 1934.88,2119.92 2059.05,2244.09 2059.05,2259.84 2047.24,2271.65 2047.24,2287.4 2275.59,2515.75 2275.59,2673.23 2251.97,2696.85 2251.97,2819.14 ; 2251.97,2814.96 v1(2251.97,2917.32) v1@2251.97,2918.31 ; v2(2381.89,3669.29) 2381.89,3696.85 2460.63,3775.59 v2(2460.63,3826.77) U11.38@2460.63,3901.57
  Top Layer w7.87: v1@2251.97,2918.31 U3.G7@2271.65,2937.99
  MidLayer1 w5: v2(1362.2,3850.39) 1362.2,3830.71 1468.5,3724.41 2326.77,3724.41 v2(2381.89,3669.29)
  MidLayer2 w5: v1(2291.34,3271.65) 2346.46,3326.77 2346.46,3385.83 2357.28,3396.65 2357.28,3416.34 2397.64,3456.69 2425.2,3456.69 2448.82,3480.32 2472.44,3480.32 2480.31,3488.19 2480.31,3507.87 2468.5,3519.69 2468.5,3673.23 2456.69,3685.04 2456.69,3704.72 2460.63,3708.66 v2(2460.63,3826.77)
  MidLayer3 w5: v1(2251.97,2917.32) 2232.28,2897.64 2192.91,2897.64 2129.92,2960.63 2129.92,3149.61 2251.97,3271.65 v1(2291.34,3271.65)
BUS_D16: U4.F20 U8.2 U12.7 | length 3737.9
  Top Layer w7.87: U4.F20@1779.53,1767.72 v1(1799.21,1787.4)
  MidLayer3 w5: v1(1799.21,1787.4) 1818.9,1807.09 1818.9,2027.56 1818.9,2043.31 1818.9,2059.06 1830.71,2070.87 1893.7,2070.87 1929.13,2106.3 1929.13,2145.67 2015.75,2232.28 2015.75,2263.78 2027.56,2275.59 2027.56,2295.27 2051.18,2318.9 2051.18,2712.6 2086.61,2748.03 2488.19,2748.03 2791.34,3051.18 2791.34,3236.22 2791.34,3381.89 2838.58,3429.13 v2(2838.58,3500) ; v2(2051.18,3665.35) 2051.18,3578.74 2098.43,3531.5 2098.43,3519.68 2118.11,3500 v2(2118.11,3405.51)
  Bottom Layer w5: v2(2051.18,3665.35) 2086.61,3629.92 2763.78,3629.92 2826.77,3566.93 2826.77,3529.53 2838.58,3517.72 v2(2838.58,3500) 2818.9,3500 2807.09,3488.19 U12.7@2807.09,3452.76 ; v2(2118.11,3405.51) U8.2@2118.11,3452.76
BUS_D17: U4.F18 U8.4 U12.8 | length 3761.3
  Top Layer w7.87: U4.F18@1700.79,1767.72 v1(1720.47,1787.4)
  MidLayer3 w5: v1(1720.47,1787.4) 1740.16,1807.09 1740.16,2027.56 1740.16,2039.37 1740.16,2051.18 1759.84,2070.87 1779.53,2070.87 1952.76,2244.09 1952.76,2263.78 1964.57,2275.59 1964.57,2299.21 1996.06,2330.71 1996.06,2724.41 2043.31,2771.65 2480.31,2771.65 2767.72,3059.06 2767.72,3389.76 2807.09,3429.13 v2(2807.09,3523.62) ; v2(2019.68,3665.35) 2019.68,3590.55 2074.8,3535.43 2074.8,3519.68 2055.12,3500 v2(2055.12,3405.51)
  Bottom Layer w5: v2(2019.68,3665.35) 2066.93,3618.11 2696.85,3618.11 2751.97,3562.99 2751.97,3543.31 2771.65,3523.62 v2(2807.09,3523.62) 2807.09,3503.94 2775.59,3472.44 U12.8@2775.59,3452.76 ; v2(2055.12,3405.51) U8.4@2055.12,3452.76
BUS_D18: U4.F16 U8.5 U12.9 | length 3808.6
  Top Layer w7.87: U4.F16@1622.05,1767.72 v1(1641.73,1787.4)
  MidLayer3 w5: v1(1641.73,1787.4) 1661.42,1807.09 1661.42,2027.56 1661.42,2039.37 1661.42,2114.17 1688.98,2141.73 1787.4,2141.73 1889.76,2244.09 1889.76,2263.78 1901.57,2275.59 1901.57,2299.21 1917.32,2314.96 1917.32,2669.29 1933.07,2685.04 1933.07,2700.79 2027.56,2795.28 2472.44,2795.28 2744.09,3066.93 2744.09,3468.5 v2(2775.59,3500) ; v2(1988.19,3665.35) 1988.19,3566.93 2042.85,3512.27 2043.31,3512.27 2043.31,3496.06 2023.62,3476.38 v2(2023.62,3405.51)
  Bottom Layer w5: v2(1988.19,3665.35) 2047.24,3606.3 2688.98,3606.3 2732.28,3562.99 2732.28,3539.37 2724.41,3531.5 2724.41,3515.75 2740.16,3500 2744.09,3500 ; v2(2023.62,3405.51) U8.5@2023.62,3452.76 ; U12.9@2744.09,3452.76 2744.09,3500 ; v2(2775.59,3500) 2744.09,3500
BUS_D19: U4.F14 U8.7 U12.10 | length 3756.9
  Top Layer w7.87: U4.F14@1543.31,1767.72 v1(1562.99,1787.4)
  MidLayer3 w5: v1(1562.99,1787.4) 1582.68,1807.09 1582.68,2027.56 1582.68,2039.37 1582.68,2066.93 1682.09,2166.34 1772.64,2166.34 1826.77,2220.47 1826.77,2263.78 1838.58,2275.59 1838.58,2299.21 1858.27,2318.9 1858.27,2673.23 1874.02,2688.98 1874.02,2704.72 1988.19,2818.9 2464.57,2818.9 2712.6,3066.93 ; v2(1956.69,3665.35) 1956.69,3535.43 1980.31,3511.81 1980.31,3496.06 1960.63,3476.38 v2(1960.63,3405.51) ; 2712.46,3066.93 v2(2712.6,3500)
  Bottom Layer w5: v2(1956.69,3665.35) 2027.56,3594.49 2637.8,3594.49 2712.6,3519.69 v2(2712.6,3500) U12.10@2712.6,3452.76 ; v2(1960.63,3405.51) U8.7@1960.63,3452.76
BUS_D20: U4.H14 U8.8 U12.13 | length 3864.5
  Top Layer w7.87: U4.H14@1543.31,1688.98 v1@1562.99,1708.66
  MidLayer3 w5: v1(1565.94,1708.66) 1543.31,1728.35 1543.31,2027.56 1543.31,2039.37 1543.31,2043.31 1677.17,2177.17 1759.84,2177.17 1803.15,2220.47 1803.15,2263.78 1791.34,2275.59 1791.34,2295.27 1838.58,2342.52 1838.58,2669.29 1826.77,2681.1 1826.77,2696.85 2027.56,2897.64 2106.3,2897.64 2129.92,2874.02 2314.96,2874.02 2342.52,2901.57 2342.52,2956.69 2362.2,2976.38 2468.5,2976.38 2507.87,3015.75 2539.37,3015.75 2590.55,3066.93 2590.55,3370.08 2570.87,3389.76 2570.87,3421.26 2618.11,3468.5 v2(2618.11,3523.62) ; v2(1925.2,3665.35) 1925.2,3555.12 1909.45,3539.37 1909.45,3519.68 1929.13,3500 v2(1929.13,3377.95)
  Bottom Layer w5: v2(1925.2,3665.35) 2007.87,3582.68 2559.06,3582.68 v2(2618.11,3523.62) 2618.11,3500 U12.13@2618.11,3452.76 ; v2(1929.13,3377.95) U8.8@1929.13,3452.76
BUS_D21: U4.F12 U8.10 U12.14 | length 3709.8
  Top Layer w7.87: v1(1444.88,1787.4) U4.F12@1464.57,1767.72
  MidLayer3 w5: v1(1444.88,1787.4) 1425.2,1807.09 1425.2,2027.56 1425.2,2039.37 1425.2,2177.17 1480.31,2232.28 1688.98,2232.28 1700.79,2244.09 1700.79,2263.78 1712.6,2275.59 1712.6,2291.34 1751.97,2330.71 1751.97,2708.66 1992.13,2948.82 2078.74,2948.82 2118.11,2988.19 2118.11,3153.54 2145.67,3181.1 2263.78,3299.21 2523.62,3299.21 2566.93,3342.52 2566.93,3362.2 2547.24,3381.89 2547.24,3429.13 2586.61,3468.5 v2(2586.61,3500) ; v2(1866.14,3405.51) 1866.14,3500 1885.83,3519.68 1885.83,3535.43 1893.7,3543.31 v2(1893.7,3665.35)
  Bottom Layer w5: v2(1866.14,3405.51) U8.10@1866.14,3452.76 ; v2(1893.7,3665.35) 1988.19,3570.87 2535.43,3570.87 2586.61,3519.69 v2(2586.61,3500) U12.14@2586.61,3452.76
BUS_D22: U4.F11 U8.11 U12.15 | length 3667.6
  Top Layer w7.87: v1(1405.51,1787.4) U4.F11@1425.2,1767.72
  MidLayer3 w5: v1(1405.51,1787.4) 1385.83,1807.09 1385.83,2027.56 1385.83,2039.37 1385.83,2200.79 1488.19,2303.15 1704.72,2303.15 1740.16,2338.58 1740.16,2716.54 1984.25,2960.63 2070.87,2960.63 2106.3,2996.06 2106.3,3200.79 2216.54,3311.02 2496.06,3311.02 v1(2543.31,3358.27) ; v2(1834.65,3405.51) 1834.65,3476.38 1854.33,3496.06 1854.33,3511.81 1846.46,3519.69 1846.46,3566.93 1862.2,3582.68 v2(1862.2,3665.35)
  Bottom Layer w5: v2(1834.65,3405.51) U8.11@1834.65,3452.76 ; v2(1862.2,3665.35) 1968.5,3559.06 2507.87,3559.06 2535.43,3531.5 2535.43,3515.75 2555.12,3496.06 U12.15@2555.12,3452.76 2555.12,3417.32 2555.12,3393.7 2543.31,3381.89 v1(2543.31,3358.27)
BUS_D23: U4.F10 U8.13 U12.16 | length 3786.4
  Top Layer w7.87: v1(1366.14,1787.4) U4.F10@1385.83,1767.72
  MidLayer3 w5: 1344.95,1918.83 1346.46,1917.32 1346.46,1807.09 v1(1366.14,1787.4) ; 1346.46,1920.34 1298.3,1968.49 1298.3,2169.96 1387.65,2259.31 1387.65,2265.6 1437.01,2314.96 1641.73,2314.96 1700.79,2374.02 1700.79,2700.79 1812.99,2812.99 1972.44,2972.44 2062.99,2972.44 2094.49,3003.94 2094.49,3204.72 2212.6,3322.83 2480.31,3322.83 2527.56,3370.08 2527.56,3381.89 ; v2(1771.65,3377.95) 1771.65,3429.13 1811.02,3468.5 1811.02,3507.87 1830.71,3527.56 v2(1830.71,3665.35) ; 2527.56,3369.83 v2(2527.56,3401.57)
  Bottom Layer w5: v2(1771.65,3377.95) U8.13@1771.65,3452.76 ; v2(1830.71,3665.35) 1948.82,3547.24 2496.06,3547.24 2511.81,3531.5 2511.81,3515.75 2503.94,3507.87 2503.94,3492.13 2523.62,3472.44 U12.16@2523.62,3452.76 2527.56,3448.82 v2(2527.56,3401.57)
BUS_D24: U4.E8 U8.42 U12.29 | length 4164.1
  Top Layer w7.87: v1(1287.4,1826.77) U4.E8@1307.09,1807.09
  MidLayer2 w5: v1(1287.4,1826.77) 1267.72,1846.46 1267.72,2007.94 1286.7,2026.92 1286.7,2227.64 1397.64,2338.58 1606.3,2338.58 1618.11,2350.39 1618.11,2653.54 1724.41,2759.84 2011.81,2759.84 2043.31,2791.34 2043.31,2968.5 2106.3,3031.5 2106.3,3236.22 2354.33,3484.25 2354.33,3507.87 2346.46,3515.75 2346.46,3696.85 2377.95,3728.35 2377.95,3834.65 2444.88,3901.57 2472.77,3901.57 v2(2523.62,3952.42) ; v2(1771.65,3948.82) 1771.65,3850.39 1830.71,3791.34 v2(1830.71,3704.72)
  Bottom Layer w5: U8.42@1771.65,3901.57 v2(1771.65,3948.82) ; v2(1830.71,3704.72) 1933.07,3807.09 2476.38,3807.09 2523.62,3854.33 v2(2523.62,3952.42)
BUS_D25: U4.F8 U8.44 U12.30 | length 4214
  Top Layer w7.87: v1(1287.4,1787.4) U4.F8@1307.09,1767.72
  MidLayer2 w5: v2(1834.65,3948.82) 1834.65,3854.33 1862.2,3826.77 v2(1862.2,3704.72)
  MidLayer3 w5: v1(1287.4,1787.4) 1267.71,1807.09 1267.72,1941.14 1267.72,2002.12 1278.3,2012.7 1278.3,2219.24 1338.58,2279.53 1338.58,2291.34 1385.83,2338.58 1633.86,2338.58 1637.8,2342.52 1637.8,2676.18 1647.64,2686.02 1647.64,2694.88 2003.94,3051.18 2031.5,3051.18 2070.87,3090.55 2070.87,3212.6 2204.72,3346.46 2440.94,3346.46 2472.44,3377.95 2472.44,3385.83 2484.25,3397.64 2484.25,3417.32 2490.16,3423.23 2543.31,3476.38 2543.31,3507.87 2535.43,3515.75 2535.43,3661.42 2562.99,3688.98 2562.99,3830.71 2574.8,3842.52 2574.8,3858.27 2555.12,3877.95 v2(2555.12,3952.76)
  Bottom Layer w5: U8.44@1834.65,3901.57 v2(1834.65,3948.82) ; v2(1862.2,3704.72) 1952.76,3795.28 2519.68,3795.28 2543.31,3818.9 2543.31,3834.65 2535.43,3842.52 2535.43,3862.2 U12.30@2555.12,3881.89 ; U12.30@2555.12,3901.57 v2(2555.12,3952.76)
BUS_D26: U4.F9 U8.45 U12.31 | length 4118.2
  Top Layer w7.87: v1(1326.77,1787.4) U4.F9@1346.46,1767.72
  MidLayer2 w5: v2(1866.14,3948.82) 1866.14,3877.95 1885.83,3858.27 1885.83,3842.52 1877.95,3834.65 1877.95,3818.9 1893.7,3803.15 v2(1893.7,3704.72)
  MidLayer3 w5: v1(1326.77,1787.4) 1307.08,1807.09 1307.09,1945.56 1288.3,1964.35 1288.3,2174.1 1362.2,2248 1362.2,2263.78 1354.33,2271.65 1354.33,2291.34 1389.76,2326.77 1637.8,2326.77 1651.57,2340.55 1651.57,2671.26 1964.57,2984.25 2051.18,2984.25 2082.68,3015.75 2082.68,3209.65 2089.57,3216.54 2207.68,3334.65 2476.38,3334.65 2511.81,3370.08 2511.81,3389.76 2507.87,3393.7 2507.87,3417.32 2566.93,3476.38 2566.93,3507.87 2574.8,3515.75 2574.8,3590.55 2590.55,3606.3 2590.55,3677.17 2582.68,3685.04 2582.68,3704.72 2586.61,3708.66 v2(2586.61,3826.77)
  Bottom Layer w5: U8.45@1866.14,3901.57 v2(1866.14,3948.82) ; v2(1893.7,3704.72) 1972.44,3783.46 2543.31,3783.46 v2(2586.61,3826.77) U12.31@2586.61,3901.57
BUS_D27: U4.F13 U8.47 U12.32 | length 4233.8
  Top Layer w7.87: v1(1484.25,1787.4) U4.F13@1503.94,1767.72
  MidLayer2 w5: v2(1925.2,3704.72) 1925.2,3818.9 1948.82,3842.52 1948.82,3858.27 1929.13,3877.95 v2(1929.13,3972.44)
  MidLayer3 w5: v1(1484.25,1787.4) 1464.57,1807.09 1464.57,2027.56 1464.57,2039.37 1464.57,2051.18 1448.82,2066.93 1448.82,2181.1 1488.19,2220.47 1716.53,2220.47 1740.16,2244.09 ; 1736.22,2240.16 1740.16,2244.09 ; v2(2618.11,3850.39) 2618.11,3708.66 2622.05,3704.72 2622.05,3685.04 2614.17,3677.17 2614.17,3551.18 2598.43,3535.43 2598.43,3515.75 2606.3,3507.87 2606.3,3472.44 2559.06,3425.2 2559.06,3385.83 2578.74,3366.14 2578.74,3149.61 2523.62,3094.49 2480.31,3094.49 2468.5,3082.68 2468.5,3027.56 2456.69,3015.75 2377.95,3015.75 2318.9,2956.69 2318.9,2905.51 2299.21,2885.83 2137.8,2885.83 2114.17,2909.45 1972.44,2909.45 1763.78,2700.79 1763.78,2322.83 1728.35,2287.4 1728.35,2275.59 1740.16,2263.78 1740.16,2244.09
  Bottom Layer w5: v2(1925.2,3704.72) 1992.13,3771.65 2559.05,3771.65 2618.11,3830.71 v2(2618.11,3850.39) U12.32@2618.11,3901.57 ; U8.47@1929.13,3901.57 v2(1929.13,3972.44)
BUS_D28: U4.F15 U8.48 U12.35 | length 4327.2
  Top Layer w7.87: U4.F15@1582.68,1767.72 v1(1602.36,1787.4)
  MidLayer2 w5: v2(1956.69,3704.72) 1956.69,3795.28 1980.31,3818.9 1980.31,3834.65 1960.63,3854.33 v2(1960.63,3972.44)
  MidLayer3 w5: v1(1602.36,1787.4) 1622.05,1807.09 1622.05,2027.56 1622.05,2039.37 1622.05,2090.55 1685.04,2153.54 1779.52,2153.54 1866.14,2240.16 1866.14,2263.78 1854.33,2275.59 1854.33,2287.4 1901.57,2334.65 1901.57,2669.29 1885.83,2685.04 1885.83,2696.85 1996.06,2807.09 2468.5,2807.09 2732.28,3070.87 2732.28,3507.87 2724.41,3515.75 2724.41,3531.49 2732.28,3539.37 2732.28,3559.06 2716.54,3574.8 2716.54,3677.17 2708.66,3685.04 2708.66,3704.72 2712.6,3708.66 2712.6,3799.21 2732.28,3818.9 2732.28,3834.65 2712.6,3854.33 v2(2712.6,3952.76)
  Bottom Layer w5: v2(1956.69,3704.72) 2011.81,3759.84 2618.11,3759.84 2712.6,3854.33 U12.35@2712.6,3901.57 v2(2712.6,3952.76) ; v2@1956.69,3972.44 v2(1960.63,3972.44) U8.48@1960.63,3901.57
BUS_D29: U4.F17 U8.50 U12.36 | length 4296.7
  Top Layer w7.87: U4.F17@1661.42,1767.72 v1(1681.1,1787.4)
  MidLayer2 w5: v2(1988.19,3704.72) 1988.19,3763.78 2043.31,3818.9 2043.31,3834.65 2023.62,3854.33 v2(2023.62,3948.82)
  MidLayer3 w5: v1(1681.1,1787.4) 1700.79,1807.09 1700.79,1917.32 1724.41,1940.94 1724.41,2027.56 1724.41,2039.37 1724.41,2055.12 1751.97,2082.68 1767.72,2082.68 1929.13,2244.09 1929.13,2263.78 1917.32,2275.59 1917.32,2287.4 1964.57,2334.65 1964.57,2669.29 1952.76,2681.1 1952.76,2700.79 2035.43,2783.46 2476.38,2783.46 2755.91,3062.99 2755.91,3393.7 2795.28,3433.07 2795.28,3507.87 2779.53,3523.62 2771.65,3523.62 2751.97,3543.31 2751.97,3559.06 2740.16,3570.87 2740.16,3677.17 2748.03,3685.04 2748.03,3704.72 2744.09,3708.66 2744.09,3822.83 2763.78,3842.52 2763.78,3858.27 2744.09,3877.95 v2(2744.09,3976.38)
  Bottom Layer w5: v2(1988.19,3704.72) 2031.5,3748.03 2661.42,3748.03 2732.28,3818.9 2732.28,3834.65 2724.41,3842.52 2724.41,3862.2 2744.09,3881.89 U12.36@2744.09,3901.57 v2(2744.09,3976.38) ; U8.50@2023.62,3901.57 v2(2023.62,3948.82)
BUS_D30: U4.F19 U8.51 U12.37 | length 4178
  Top Layer w7.87: U4.F19@1740.16,1767.72 v1(1759.84,1787.4)
  MidLayer2 w5: v2(2019.68,3704.72) 2019.68,3767.72 2066.93,3814.96 2066.93,3834.65 2074.8,3842.52 2074.8,3858.27 2055.12,3877.95 v2(2055.12,3948.82)
  MidLayer3 w5: v1(1759.84,1787.4) 1779.53,1807.09 1779.53,2027.56 1779.53,2039.37 1779.53,2047.24 1944.88,2212.6 1960.63,2212.6 1992.12,2244.09 1992.12,2263.78 1980.31,2275.59 1980.31,2295.27 2039.37,2354.33 2039.37,2720.47 2078.74,2759.84 2484.25,2759.84 2778.54,3054.13 2778.54,3384.84 2818.9,3425.2 2818.9,3507.87 2826.77,3515.75 2826.77,3566.93 2779.53,3614.17 2779.53,3677.17 2771.65,3685.04 2771.65,3704.72 2775.59,3708.66 2775.59,3795.28 2795.28,3814.96 2795.28,3834.65 2775.59,3854.33 v2(2775.59,3952.76)
  Bottom Layer w5: v2(2019.68,3704.72) 2051.18,3736.22 2669.29,3736.22 2755.9,3822.83 2755.9,3834.65 2775.59,3854.33 v2(2775.59,3952.76) ; U8.51@2055.12,3901.57 v2(2055.12,3948.82)
BUS_D31: U4.F21 U8.53 U12.38 | length 4203.5
  Top Layer w7.87: U4.F21@1818.9,1767.72 v1(1838.58,1787.4)
  MidLayer2 w5: v2(2051.18,3704.72) 2051.18,3755.91 2137.8,3842.52 2137.8,3862.2 2118.11,3881.89 v2(2118.11,3948.82)
  MidLayer3 w5: v1(1838.58,1787.4) 1858.27,1807.09 1858.27,2027.56 1858.27,2039.37 1874.02,2055.12 1897.64,2055.12 1964.57,2122.05 1964.57,2153.54 2055.12,2244.09 2055.12,2263.78 2043.3,2275.59 2043.3,2291.34 2062.99,2311.02 2062.99,2704.72 2094.49,2736.22 2492.12,2736.22 2803.15,3047.25 2803.15,3377.96 2858.27,3433.07 2858.27,3507.87 2850.39,3515.75 2850.39,3531.5 2866.14,3547.24 2866.14,3562.99 2803.15,3625.98 2803.15,3677.17 2811.02,3685.04 2811.02,3704.72 2807.09,3708.66 2807.09,3822.83 2826.77,3842.52 2826.77,3858.27 2807.09,3877.95 v2(2807.09,3952.76)
  Bottom Layer w5: v2(2051.18,3704.72) 2070.87,3724.41 2704.72,3724.41 2795.28,3814.96 2795.28,3834.65 2787.4,3842.52 2787.4,3862.2 2807.09,3881.89 v2(2807.09,3952.76) ; U8.53@2118.11,3901.57 v2(2118.11,3948.82)
BUS_FLASH_NBUSY: U3.A4 U4.L26 | length 1887.3
  Top Layer w5: U4.L26@2015.75,1570.87 2043.31,1570.87 2062.99,1551.18 2078.74,1551.18 2094.49,1551.18 2204.72,1551.18 2287.4,1633.86 2287.4,2011.81 2346.46,2070.87 2433.07,2157.48 2433.07,2263.78 2425.2,2271.65 2425.2,2291.34 2452.76,2318.9 2452.76,2606.3 2511.81,2665.35 2511.81,2818.9 2570.87,2877.95 2570.87,2996.07 v1(2527.56,3035.43)
  Top Layer w7.87: U3.A4@2507.87,3056.1 v1(2527.56,3035.43)
BUS_FLASH_NCS: U3.F2 U4.A19 | length 1710.9
  Top Layer w5: U4.A19@1740.16,1964.57 1740.16,2027.56 1740.16,2039.37 1740.16,2060.04 1748.03,2067.91 1748.03,2129.92 1807.09,2188.98 1807.09,2259.84 1795.27,2271.65 1795.27,2291.34 1807.09,2303.15 1842.52,2303.15 1862.2,2322.83 1885.82,2322.83 1917.57,2354.58 1945.13,2354.58 1972.44,2381.89 2000,2381.89 2075.79,2457.68 2075.79,2625.98 2055.12,2646.65 2055.12,2716.54 2114.17,2775.59 2114.17,2956.69 2129.92,2972.44 2129.92,3122.05 2212.6,3204.72 2271.65,3204.72 2291.34,3185.04 2291.34,3161.42 2299.21,3153.54 v1(2330.71,3153.54) ; U3.F2@2310.03,3134.85 U3.F2@2311.02,3134.84
  Top Layer w7.87: U3.F2@2311.02,3134.84 v1(2330.71,3153.54)
BUS_FLASH_NRESET: U3.B5 U4.N24 | length 2591.6
  Top Layer w7.87: U4.N24@1937.01,1492.13 v1(1956.69,1511.81) ; v1(2448.82,3035.43) U3.B5@2468.5,3016.73
  MidLayer1 w5: v1(1956.69,1511.81) 2078.74,1511.81 2090.55,1511.81 2181.1,1511.81 2240.16,1570.87 2240.16,1657.48 2322.83,1740.16 2322.83,2090.55 2456.69,2224.41 2496.06,2224.41 2519.68,2248.03 2519.68,2263.78 2543.31,2287.4 2543.31,2740.16 2559.06,2755.91 2559.06,3000 2543.31,3015.75 2507.87,3015.75 2488.19,3035.43 v1(2448.82,3035.43)
  Bottom Layer w5: v1(2011.81,3149.61) 2031.5,3129.92 2169.29,3129.92 2181.1,3118.11 2181.1,3102.36 2200.79,3082.68 2232.28,3082.68 2244.09,3094.49 2417.32,3094.49 2448.82,3062.99 v1(2448.82,3035.43)
BUS_NBE0: RN1.6 RN4.7 U4.E11 U7.15 U11.39 | length 4233.4
  Top Layer w5: U7.15@1771.65,3452.75 v2(1771.65,3503.93) ; v2(2429.13,3850.39) U11.39@2429.13,3901.57
  Top Layer w7.87: v1(1405.51,1826.77) U4.E11@1425.2,1807.09
  MidLayer2 w5: v1(1405.51,1826.77) 1385.83,1846.46 1385.83,2027.56 1385.83,2039.37 1385.83,2200.79 1425.2,2240.16 1425.2,2259.84 1413.38,2271.65 1413.38,2283.46 1444.88,2314.96 1614.17,2314.96 1640.75,2341.54 1640.75,2597.44 1700.79,2657.48 1700.79,2700.79 1736.22,2736.22 2023.62,2736.22 2102.36,2814.96 2102.36,2988.19 2129.92,3015.75 2129.92,3228.35 2370.08,3468.5 2417.32,3468.5 2440.94,3492.13 2440.94,3507.87 2448.82,3515.75 2448.82,3531.5 2425.2,3555.12 2425.2,3677.17 2433.07,3685.04 2433.07,3704.72 2429.13,3708.66 v2(2429.13,3850.39) ; v1(1742.14,3311.02) 1742.14,3376 1771.65,3405.51 v2(1771.65,3503.93)
  MidLayer3 w5: v2(1771.65,3503.93) 1771.65,3657.49 1748.03,3681.1 1748.03,3767.72 1862.2,3881.89 2397.64,3881.89 v2(2429.13,3850.39)
  Bottom Layer w5: RN1.6@1688.58,3311.02 RN4.7@1779.92,3311.02
BUS_NBE1: RN3.5 RN5.8 U4.E10 U7.39 U11.40 | length 3965
  Top Layer w5: U7.39@1803.14,3901.57 v2(1803.14,3850.39) 1803.14,3818.9 1818.89,3803.15 2374.02,3803.15 v2(2397.64,3826.77) U11.40@2397.64,3901.57
  Top Layer w7.87: v1(1366.14,1826.77) U4.E10@1385.83,1807.09
  MidLayer2 w5: v1(1366.14,1826.77) 1346.46,1846.46 1346.46,1948.82 1322.83,1972.44 1322.83,2027.56 1322.83,2043.31 1322.83,2059.06 1346.46,2082.68 1346.46,2200.79 1385.83,2240.16 1385.83,2259.84 1397.64,2271.65 1397.64,2283.47 1440.94,2326.77 1610.24,2326.77 1628.29,2344.83 1628.29,2647.98 1728.35,2748.03 2015.75,2748.03 2090.55,2822.83 2090.55,2996.06 2118.11,3023.62 2118.11,3232.28 2366.14,3480.32 2409.45,3480.32 2417.32,3488.19 2417.32,3507.87 2405.51,3519.68 2405.51,3673.23 2393.7,3685.04 2393.7,3704.72 2397.64,3708.66 v2(2397.64,3826.77)
  MidLayer3 w5: v1@1617.92,4055.11 1653.55,4055.11 1708.66,4000 1708.66,3944.88 v2@1803.15,3850.39
  Bottom Layer w5: RN3.5@1586.22,4055.11 RN5.8@1677.17,4055.11
  other v1: 1618.11,4055.11
BUS_NBE2: RN1.5 RN4.8 U4.E17 U8.15 U12.39 | length 4873
  Top Layer w7.87: U4.E17@1661.42,1807.09 v1(1681.1,1826.77)
  MidLayer2 w5: v1(1681.1,1826.77) 1700.79,1846.46 1700.79,1948.82 1724.41,1972.44 1724.41,2027.56 1724.41,2039.37 1724.41,2055.12 1901.57,2232.28 1921.26,2232.28 1984.25,2295.28 1984.25,2677.17 1992.13,2685.04 1992.13,2696.85 2007.87,2712.6 2035.43,2712.6 2125.98,2803.15 2125.98,2976.38 2181.1,3031.5 2181.1,3177.17 2228.35,3224.41 2460.63,3224.41 2476.38,3208.66 2716.54,3208.66 2862.2,3354.33 2862.2,3374.02 2881.89,3393.7 2881.89,3507.87 2889.76,3515.75 2889.76,3531.5 2881.89,3539.37 2881.89,3732.28 2858.27,3755.91 2858.27,3834.65 2838.58,3854.33 v2(2838.58,3976.38)
  MidLayer3 w5: v2(1708.66,3377.95) 1708.66,3409.45 1791.34,3492.13 1791.34,3511.81 1783.46,3519.68 1783.46,3688.98 v2(1799.21,3704.72)
  Bottom Layer w5: U8.15@1708.66,3452.76 v2(1708.66,3377.95) 1708.66,3362.2 1688.98,3342.52 1688.98,3331.1 1688.58,3330.71 RN4.8@1779.53,3330.71 ; v2@1799.21,3696.85 1811.02,3685.04 2078.74,3685.04 2106.3,3712.6 2712.6,3712.6 2818.9,3818.9 2818.9,3834.65 2838.58,3854.33 U12.39@2838.58,3901.57 v2(2838.58,3976.38)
